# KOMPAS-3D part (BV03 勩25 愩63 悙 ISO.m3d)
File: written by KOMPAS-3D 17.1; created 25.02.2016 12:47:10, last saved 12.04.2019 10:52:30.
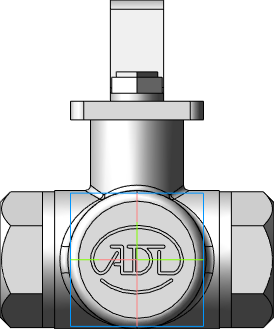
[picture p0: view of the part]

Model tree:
1. Операция без истории:3  (labels: Сталь 20  ГОСТ 1050-88)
